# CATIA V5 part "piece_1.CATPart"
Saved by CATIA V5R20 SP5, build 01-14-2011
Part number: piece_1
Bounding box of the stored display mesh (mm): x 0 to 29, y 0 to 310.485, z -30.444 to 30.444
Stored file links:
  E:\IAO_2010\iao\IAO_MMS_Groupe3\PB\jpeguet\jpeguet_IAO\jpeguet_IAO\piece_1.CATPart
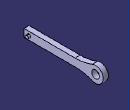
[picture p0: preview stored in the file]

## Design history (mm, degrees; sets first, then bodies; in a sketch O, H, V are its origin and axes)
Body1 (main body)
  Sketch1 on yz-plane, origin (0, 0, 0), H (0, 1, 0), V (0, 0, 1)
    line L1 (0, 0) -> (0, 15)
    line L2 (0, 15) -> (200, 15)
    arc A1 centre (200, 198.9105) radius 183.9105 from (200, 15) to (268.6248, 28.2831) ccw
    point P4 (268.6248, 28.2831)
    point P5 (268.6248, 28.2831)
    arc A2 centre (280, 0) radius 30.4849 from (268.6248, 28.2831) to (268.6248, -28.2831) cw
    arc A3 centre (200, -198.9105) radius 183.9105 from (268.6248, -28.2831) to (200, -15) ccw
    line L3 (200, -15) -> (0, -15)
    point P10 (0, -15)
    line L4 (0, -15) -> (0, 0)
    distance L3 L2 = 30
    distance L3 H = 15
    length L2 = 200
    length L3 = 200
    vertical: L1 V, L4 V
    horizontal: L2 H, L3 H
    tangency: A1 L2, A3 A2, A3 L3, A1 A2
    coincidence: P10 V, P4 P5
  Pad1: profile Sketch1, direction (1, 0, 0), length 20
  Sketch2 on end face of Pad1, origin (20, 283.753, 0), H (0, 1, 0), V (0, 0, 1)
    point P1 (-3.753, 0)
    reference projected arc E1 centre (-3.753, 0) radius 30.4849 from (-15.1282, -28.2831) to (-15.1282, 28.2831) ccw from edge [face of Pad1 from Sketch1.A2 | end face of Pad1]
    concentricity: P1 E1
  Hole1: placed by Sketch2, at (20, 280, 0) direction (-1, 0, 0), diameter 30, through (limit type 3)
  Sketch3 on end face of Pad1, origin (20, 0, 0), H (0, 1, 0), V (0, 0, 1)
    arc A1 centre (20, 0) radius 7 from (21, -6.9282) to (21, 6.9282) ccw
    point P1 (20, 0)
    line L1 (21, -6.9282) -> (21, -4)
    line L2 (21, -4) -> (19, -4)
    line L3 (19, -4) -> (19, -6.9282)
    reference projected line E1 (0, 0) -> (0, -15) from edge [face of Pad1 from Sketch1.L4 | end face of Pad1]
    line L4 (21, 4) -> (21, 6.9282)
    line L5 (19, 6.9282) -> (19, 4)
    line L6 (19, 4) -> (21, 4)
    arc A2 centre (20, 0) radius 7 from (19, 6.9282) to (19, -6.9282) ccw
    radius A1 = 7
    length L2 = 2
    distance L3 E1 = 19
    distance L2 P1 = 4
    coincidence: P1 H, A1 A2
    horizontal: L2 H
    vertical: L1 V, L3 V
  Pad2: profile Sketch3, direction (1, 0, 0), length 9
  Point1: type Center, Curve edge [end face of Pad1 | face of Pad2 from Sketch3.A1]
